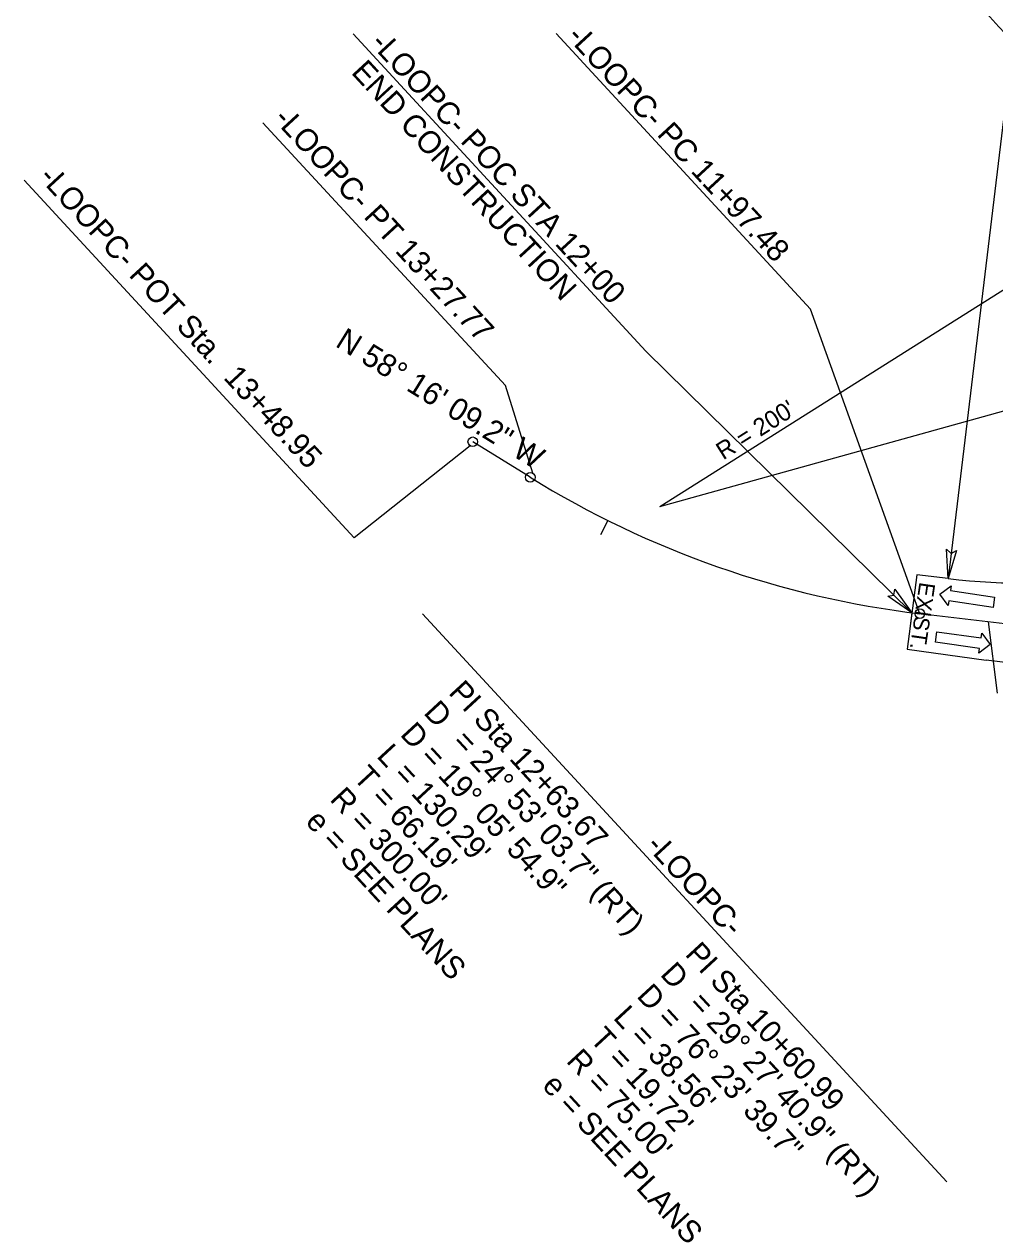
# Model space of a CAD drawing. Extents: x 1702862 to 1704514, y 793768 to 796215.
# Drawn here: x 1703439.5 to 1703743.4, y 794306.9 to 794685.6 of the extents above; entities that cross this region are included whole.
import ezdxf

# ---------------------------------------------------------------- set-up
doc = ezdxf.new("R2010")
doc.units = 0
for name, color, linetype in [('Prop Conc 2ft 6in Curb and Gutter', 7, 'Continuous'), ('Prop Dimension', 7, 'Continuous'), ('Prop Dimension Text', 7, 'Continuous'), ('Prop DSN Text', 7, 'Continuous'), ('Prop EOT', 7, 'Continuous'), ('Prop Horizontal Alignment', 7, 'Continuous'), ('Prop Horizontal Alignment Curve and Spiral Data', 7, 'Continuous'), ('Prop Horizontal Alignment Direction Label', 7, 'Continuous'), ('Prop Horizontal Alignment Station Label', 7, 'Continuous'), ('Prop Horizontal Alignment Tick Small', 7, 'Continuous'), ('Prop Lane Arrow CELL', 7, 'Continuous'), ('Prop Lane Lines', 7, 'Continuous'), ('Prop Leader Line Medium', 7, 'Continuous'), ('Prop Rem of Exist Asph Pvmt', 7, 'Continuous'), ('Prop Terminator CELL', 7, 'Continuous')]:
    doc.layers.add(name, color=color, linetype=linetype)

msp = doc.modelspace()

# ---------------------------------------------------------------- linework, layer by layer
at = {"layer": 'Prop Conc 2ft 6in Curb and Gutter'}
msp.add_arc((1702985.28, 794122.36), 970.46, 32.25438, 42.65517, dxfattribs=at)
at = {"layer": 'Prop Dimension'}
for p, q in [((1703752.73, 794710.66), (1703728.81, 794512.1)), ((1703638.54, 794534.6), (1703807.68, 794641.34)), ((1703638.54, 794534.6), (1703831.2, 794588.31))]:
    msp.add_line(p, q, dxfattribs=at)
at = {"layer": 'Prop DSN Text'}
msp.add_line((1703718.99, 794513.26), (1703716.01, 794490.01), dxfattribs=at)
at = {"layer": 'Prop EOT'}
for p, q in [((1703728.81, 794512.1), (1703718.97, 794513.28)), ((1703716.01, 794490.01), (1703740.76, 794486.48)), ((1703844.62, 794474.01), (1703740.76, 794486.48))]:
    msp.add_line(p, q, dxfattribs=at)
for centre, radius, start, end in [((1702989.11, 794124.65), 1018, 14.75888, 42.70907), ((1702989.11, 794124.65), 968, 32.4282, 42.70916), ((1703752.73, 794710.66), 200, 263.1332, 278.4921)]:
    msp.add_arc(centre, radius, start, end, dxfattribs=at)
at = {"layer": 'Prop Horizontal Alignment'}
for p, q in [((1703597.95, 794543.77), (1703579.94, 794554.91)), ((1703836.77, 794487.04), (1703719.97, 794501.07))]:
    msp.add_line(p, q, dxfattribs=at)
for centre, radius, start, end in [((1702989.11, 794124.65), 1000, 351.25916, 42.70907), ((1703755.73, 794798.93), 300, 238.2692, 263.1536)]:
    msp.add_arc(centre, radius, start, end, dxfattribs=at)
at = {"layer": 'Prop Horizontal Alignment Curve and Spiral Data'}
for p, q in [((1703606.08, 794682.77), (1703685.74, 794596.47)), ((1703514.2, 794654.8), (1703590.2, 794572.47)), ((1703439.46, 794636.83), (1703542.8, 794524.87)), ((1703564.23, 794501.06), (1703728.41, 794323.2))]:
    msp.add_line(p, q, dxfattribs=at)
at = {"layer": 'Prop Horizontal Alignment Direction Label'}
msp.add_line((1703744.31, 794476.19), (1703741.41, 794498.49), dxfattribs=at)
at = {"layer": 'Prop Horizontal Alignment Station Label'}
for p, q in [((1703719.97, 794501.07), (1703685.74, 794596.47)), ((1703598.74, 794545.04), (1703590.2, 794572.47)), ((1703579.15, 794553.63), (1703542.8, 794524.87))]:
    msp.add_line(p, q, dxfattribs=at)
for centre in [(1703579.94, 794554.91), (1703597.95, 794543.77), (1703719.97, 794501.07)]:
    msp.add_circle(centre, 1.5, dxfattribs=at)
at = {"layer": 'Prop Horizontal Alignment Tick Small'}
for p, q in [((1703622.22, 794530.27), (1703619.99, 794525.8)), ((1703717.47, 794501.38), (1703716.83, 794496.42))]:
    msp.add_line(p, q, dxfattribs=at)
at = {"layer": 'Prop Lane Arrow CELL'}
for p, q in [((1703726.17, 794507.14), (1703729.76, 794509.83)), ((1703729.76, 794509.83), (1703729.54, 794508.35)), ((1703728.82, 794503.61), (1703726.17, 794507.14)), ((1703729.04, 794505.09), (1703728.82, 794503.61)), ((1703742.89, 794502.99), (1703729.04, 794505.09)), ((1703729.54, 794508.35), (1703743.38, 794506.25)), ((1703743.38, 794506.25), (1703742.89, 794502.99)), ((1703724.8, 794492.15), (1703725.25, 794495.42)), ((1703725.25, 794495.42), (1703739.12, 794493.5)), ((1703739.12, 794493.5), (1703739.33, 794494.98)), ((1703739.33, 794494.98), (1703742.02, 794491.48)), ((1703738.67, 794490.23), (1703724.8, 794492.15)), ((1703742.02, 794491.48), (1703738.46, 794488.74)), ((1703738.46, 794488.74), (1703738.67, 794490.23))]:
    msp.add_line(p, q, dxfattribs=at)
at = {"layer": 'Prop Lane Lines'}
for radius, start in [(1006, 0.00687), (994, 359.40932), (980, 359.40932)]:
    msp.add_arc((1702989.11, 794124.65), radius, start, 42.70907, dxfattribs=at)
at = {"layer": 'Prop Leader Line Medium'}
for p, q in [((1703542.52, 794682.59), (1703634.19, 794583.29)), ((1703634.19, 794583.29), (1703717.47, 794501.38))]:
    msp.add_line(p, q, dxfattribs=at)
at = {"layer": 'Prop Rem of Exist Asph Pvmt'}
msp.add_spline([(1703779.68, 794644.96), (1703761.75, 794665.91), (1703731.32, 794699.4), (1703700.82, 794732.47), (1703669.4, 794765.36)], degree=3, dxfattribs=at)
at = {"layer": 'Prop Terminator CELL'}
for points in [[(1703731.42, 794520.85), (1703728.81, 794512.1), (1703728.3, 794521.27), (1703729.75, 794519.94)], [(1703712.14, 794508.79), (1703717.47, 794501.38), (1703709.89, 794506.58), (1703711.84, 794506.92)]]:
    msp.add_lwpolyline(points, close=True, dxfattribs=at)

# ---------------------------------------------------------------- texts
at = {"layer": 'Prop Dimension Text'}
for s, height, rotation, p in [("R = 200'", 5.5, 32.2542, (1703658.37, 794549.05)), ('EXIST.', 5, 261.6644, (1703719.86, 794511.16))]:
    msp.add_text(s, height=height, rotation=rotation, dxfattribs=at).set_placement(p)
at = {"layer": 'Prop DSN Text'}
for s, p in [('-LOOPC- POC STA 12+00', (1703547.57, 794679.44)), (' END CONSTRUCTION', (1703539.85, 794672.31))]:
    msp.add_text(s, height=7, rotation=312.7091, dxfattribs=at).set_placement(p)
at = {"layer": 'Prop Horizontal Alignment Curve and Spiral Data'}
for s, p in [('PI Sta 12+63.67', (1703572.07, 794476.17)), ('D', (1703564.27, 794469.88)), ('D = 19%%d 05\' 54.9"', (1703556.92, 794463.1)), ('= 24%%d 53\' 03.7" (RT)', (1703573.2, 794460.64)), ("L = 130.29'", (1703549.57, 794456.32)), ("T = 66.19'", (1703542.22, 794449.54)), ("R = 300.00'", (1703534.88, 794442.75)), ('e = SEE PLANS', (1703527.25, 794435.73)), ('-LOOPC-', (1703633.91, 794428.2)), ('PI Sta 10+60.99', (1703646.15, 794394.26)), ('D', (1703638.35, 794387.97)), ('D = 76%%d 23\' 39.7"', (1703631, 794381.19)), ('= 29%%d 27\' 40.9" (RT)', (1703647.28, 794378.73)), ("L = 38.56'", (1703623.65, 794374.4)), ("T = 19.72'", (1703616.3, 794367.62)), ("R = 75.00'", (1703608.96, 794360.84)), ('e = SEE PLANS', (1703601.35, 794353.03))]:
    msp.add_text(s, height=7, rotation=312.7091, dxfattribs=at).set_placement(p)
at = {"layer": 'Prop Horizontal Alignment Direction Label'}
msp.add_text('N 58%%d 16\' 09.2" W', height=7, rotation=328.2692, dxfattribs=at).set_placement((1703536.58, 794584.96))
at = {"layer": 'Prop Horizontal Alignment Station Label'}
for s, p in [('-LOOPC- PC 11+97.48', (1703609.14, 794681.55)), ('-LOOPC- PT 13+27.77', (1703517.27, 794655.79)), ('-LOOPC- POT Sta.  13+48.95', (1703443.74, 794637.5))]:
    msp.add_text(s, height=7, rotation=312.7091, dxfattribs=at).set_placement(p)

doc.saveas('drawing.dxf')
